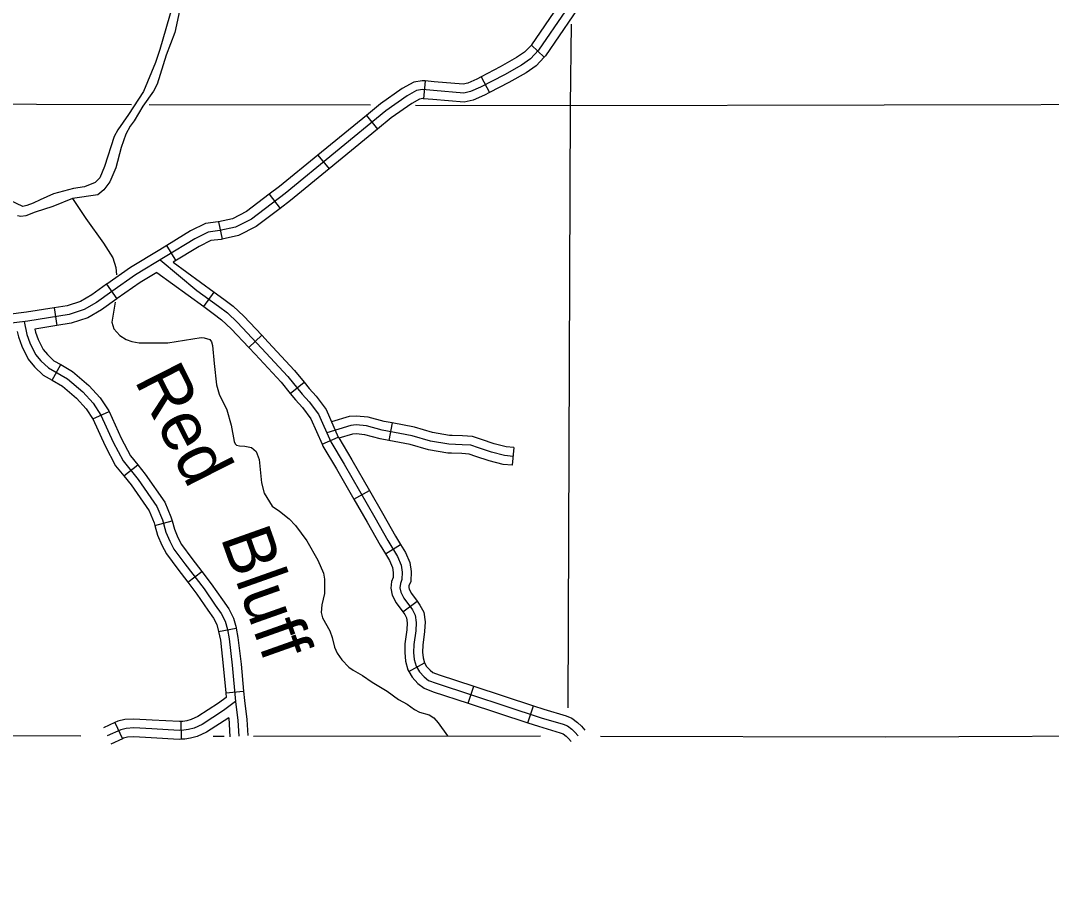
# Model space of a CAD drawing. Extents: x -19 to 366, y -4 to 359.
# Drawn here: x 129.595 to 131.239, y 197.843 to 199.218 of the extents above; entities that cross this region are included whole.
import ezdxf

# ---------------------------------------------------------------- set-up
doc = ezdxf.new("R2010")
doc.units = 0
for name, color, linetype in [('R_Alt Surface', 7, 'Continuous'), ('R_Axis Annot', 7, 'Continuous'), ('R_ROW Annot', 7, 'Continuous'), ('R_Temp Easement', 7, 'Continuous'), ('Sheet Fence', 7, 'Continuous'), ('T_Indications', 7, 'Continuous')]:
    doc.layers.add(name, color=color, linetype=linetype)

msp = doc.modelspace()

# ---------------------------------------------------------------- linework, layer by layer
at = {"layer": 'R_Alt Surface'}
for points in [[(129.0073, 198.0861), (129.0482, 198.0855), (129.434, 198.0792), (129.4695, 198.0791), (129.6913, 198.0783)], [(129.9021, 198.0778), (129.92, 198.0778)], [(129.9664, 198.0778), (130.424, 198.0784)], [(130.5198, 198.0781), (130.9745, 198.0766), (131.4426, 198.0787), (131.466, 198.0787), (131.7638, 198.0787), (132.3344, 198.0804)]]:
    msp.add_lwpolyline(points, dxfattribs=at)
at = {"layer": 'R_Axis Annot'}
for points in [[(130.472, 199.0833), (130.4736, 199.213)], [(129.4687, 199.0856), (129.7722, 199.0849)], [(129.8001, 199.0848), (130.1533, 199.084)], [(130.2248, 199.0838), (130.472, 199.0833)], [(130.472, 199.0833), (131.4723, 199.0854)], [(130.4681, 198.1228), (130.472, 199.0833)]]:
    msp.add_lwpolyline(points, dxfattribs=at)
at = {"layer": 'R_ROW Annot'}
for p, q in [((130.4096, 199.1795), (130.4302, 199.16)), ((130.2404, 199.1222), (130.2379, 199.0939)), ((130.3297, 199.1288), (130.3428, 199.1036)), ((130.1465, 199.0674), (130.1645, 199.0455)), ((130.0691, 199.004), (130.0871, 198.9821)), ((129.9917, 198.9416), (130.0089, 198.919)), ((129.9105, 198.8979), (129.9164, 198.8701)), ((129.8277, 198.8598), (129.8425, 198.8356)), ((129.7323, 198.7983), (129.7489, 198.7752)), ((129.8872, 198.7628), (129.9039, 198.7857)), ((129.6485, 198.7606), (129.6531, 198.7325)), ((129.9589, 198.6974), (129.9796, 198.7168)), ((129.6453, 198.6454), (129.6594, 198.6701)), ((130.0252, 198.624), (130.0473, 198.6419)), ((129.7106, 198.5835), (129.7365, 198.5952)), ((130.0758, 198.5433), (130.1018, 198.5547)), ((129.7598, 198.4928), (129.7819, 198.5106)), ((130.1268, 198.4555), (130.1515, 198.4697)), ((129.8093, 198.4135), (129.8367, 198.4211)), ((130.1769, 198.3686), (130.2012, 198.3833)), ((129.8617, 198.3232), (129.8843, 198.3405)), ((130.2047, 198.276), (130.2276, 198.2929)), ((129.911, 198.2447), (129.9389, 198.2501)), ((130.2145, 198.1808), (130.2393, 198.1948)), ((129.9225, 198.1468), (129.9507, 198.1494)), ((130.3089, 198.1304), (130.3178, 198.1574)), ((130.4039, 198.0992), (130.4128, 198.1261)), ((129.7457, 198.0996), (129.7576, 198.0738)), ((129.8505, 198.1014), (129.8515, 198.073))]:
    msp.add_line(p, q, dxfattribs=at)
for points in [[(130.464, 199.2602), (130.4523, 199.2419), (130.4101, 199.1801), (130.4096, 199.1795)], [(130.4641, 199.2341), (130.4212, 199.1712), (130.4082, 199.1574), (130.3937, 199.1475), (130.3669, 199.1321), (130.3286, 199.1122), (130.3125, 199.1053), (130.3018, 199.103), (130.2535, 199.1068), (130.2359, 199.1084), (130.2267, 199.1068), (130.2114, 199.0984), (130.1777, 199.0747), (130.0168, 198.9428), (129.9632, 198.9022), (129.938, 198.8892), (129.9127, 198.8838), (129.8943, 198.8815), (129.8729, 198.8708), (129.7784, 198.813), (129.7408, 198.7869), (129.7163, 198.7693), (129.6964, 198.7578), (129.6727, 198.7501), (129.6068, 198.7394), (129.2966, 198.7015)], [(130.4879, 199.2449), (130.476, 199.2262), (130.4323, 199.1623), (130.4302, 199.16)], [(130.4096, 199.1795), (130.3989, 199.1683), (130.3861, 199.1595), (130.3601, 199.1446), (130.3297, 199.1288)], [(130.4302, 199.16), (130.4175, 199.1466), (130.4012, 199.1354), (130.3737, 199.1197), (130.3428, 199.1036)], [(130.2404, 199.1222), (130.2353, 199.1227), (130.222, 199.1205), (130.2038, 199.1105), (130.1691, 199.086), (130.1465, 199.0674)], [(130.3297, 199.1288), (130.3225, 199.1251), (130.3082, 199.1189), (130.3008, 199.1173), (130.2547, 199.121), (130.2404, 199.1222)], [(130.3428, 199.1036), (130.3347, 199.0994), (130.3168, 199.0917), (130.3027, 199.0887), (130.2523, 199.0927), (130.2379, 199.0939)], [(130.2379, 199.0939), (130.2365, 199.0941), (130.2314, 199.0932), (130.2189, 199.0863), (130.1863, 199.0633), (130.1645, 199.0455)], [(130.1465, 199.0674), (130.0691, 199.004)], [(130.1645, 199.0455), (130.0871, 198.9821)], [(130.0691, 199.004), (130.0081, 198.954), (129.9917, 198.9416)], [(130.0871, 198.9821), (130.0256, 198.9317), (130.0089, 198.919)], [(129.9917, 198.9416), (129.9556, 198.9143), (129.9331, 198.9027), (129.9105, 198.8979)], [(130.0089, 198.919), (129.9708, 198.8902), (129.9428, 198.8757), (129.9164, 198.8701)], [(129.9105, 198.8979), (129.9103, 198.8979), (129.8901, 198.8953), (129.866, 198.8832), (129.817, 198.8533)], [(129.9164, 198.8701), (129.915, 198.8698), (129.8985, 198.8677), (129.8798, 198.8584), (129.8387, 198.8333)], [(129.817, 198.8533), (129.7706, 198.8249), (129.7326, 198.7985), (129.7323, 198.7983)], [(129.8179, 198.8371), (129.876, 198.7885), (129.9108, 198.7631), (129.925, 198.7525), (129.9409, 198.7371), (129.9793, 198.6963), (130.0213, 198.6514), (130.0443, 198.6231), (130.0555, 198.6106), (130.0703, 198.5911), (130.0898, 198.5468), (130.111, 198.5114), (130.1601, 198.4263), (130.1807, 198.3896), (130.1961, 198.3642), (130.202, 198.3506), (130.2038, 198.3394), (130.2032, 198.3276), (130.2007, 198.3211), (130.1998, 198.3143), (130.2013, 198.3075), (130.2063, 198.2977), (130.2199, 198.2794), (130.2243, 198.2708), (130.2261, 198.2593), (130.2252, 198.246), (130.2222, 198.2241), (130.2219, 198.2114), (130.2228, 198.2002), (130.2261, 198.1893), (130.2311, 198.1804), (130.2385, 198.1724), (130.2456, 198.1668), (130.258, 198.1621), (130.4251, 198.1071), (130.4603, 198.0968), (130.4671, 198.0941), (130.4742, 198.0888), (130.4792, 198.0841), (130.484, 198.0782)], [(129.8387, 198.8333), (129.9039, 198.7857)], [(129.8125, 198.8172), (129.7861, 198.8011), (129.749, 198.7753), (129.7489, 198.7752)], [(129.8125, 198.8172), (129.8872, 198.7628)], [(129.7323, 198.7983), (129.7086, 198.7812), (129.6906, 198.7708), (129.6693, 198.764), (129.6485, 198.7606)], [(129.7489, 198.7752), (129.724, 198.7573), (129.7022, 198.7447), (129.676, 198.7363), (129.6531, 198.7325)], [(129.9039, 198.7857), (129.9193, 198.7745), (129.9342, 198.7633), (129.951, 198.7471), (129.9796, 198.7168)], [(129.6485, 198.7606), (129.6048, 198.7535), (129.5501, 198.7468)], [(129.8872, 198.7628), (129.9024, 198.7517), (129.9158, 198.7416), (129.9308, 198.7271), (129.9589, 198.6974)], [(129.6008, 198.7386), (129.6054, 198.7181), (129.6101, 198.7048), (129.6191, 198.6864), (129.6277, 198.6762), (129.6398, 198.6649), (129.67, 198.6476), (129.6943, 198.6269), (129.7107, 198.6085), (129.7234, 198.5897), (129.7429, 198.5467), (129.7586, 198.5169), (129.7826, 198.4871), (129.8126, 198.4441), (129.8215, 198.4227), (129.827, 198.4031), (129.8333, 198.3885), (129.8398, 198.376), (129.857, 198.3527), (129.8878, 198.3125), (129.9056, 198.2869), (129.9152, 198.2733), (129.9212, 198.2611), (129.9249, 198.2477), (129.9277, 198.2328), (129.9325, 198.1913), (129.938, 198.133), (129.9417, 198.103), (129.9432, 198.0778)], [(129.5897, 198.723), (129.5917, 198.7142), (129.597, 198.6993), (129.6071, 198.6786), (129.6174, 198.6664), (129.6313, 198.6534), (129.6453, 198.6454)], [(129.6531, 198.7325), (129.618, 198.7268)], [(129.618, 198.7268), (129.619, 198.7221), (129.6232, 198.7103), (129.6311, 198.6942), (129.638, 198.686), (129.6483, 198.6764), (129.6594, 198.6701)], [(129.9796, 198.7168), (129.9897, 198.7061), (130.032, 198.6608), (130.0473, 198.6419)], [(129.9589, 198.6974), (129.969, 198.6866), (130.0105, 198.6421), (130.0252, 198.624)], [(129.6594, 198.6701), (129.6782, 198.6593), (129.7042, 198.637), (129.7219, 198.6172), (129.7358, 198.5967), (129.7365, 198.5952)], [(129.6453, 198.6454), (129.6618, 198.636), (129.6843, 198.6167), (129.6995, 198.5997), (129.7109, 198.5828), (129.7106, 198.5835)], [(130.0473, 198.6419), (130.0551, 198.6323), (130.0665, 198.6197), (130.0826, 198.5984), (130.1018, 198.5547)], [(130.0252, 198.624), (130.0335, 198.6138), (130.0446, 198.6016), (130.058, 198.5839), (130.0758, 198.5433)], [(129.7365, 198.5952), (129.7557, 198.5529), (129.7705, 198.5247), (129.7819, 198.5106)], [(129.7106, 198.5835), (129.7302, 198.5404), (129.7467, 198.509), (129.7598, 198.4928)], [(130.0758, 198.5433), (130.0771, 198.5403), (130.0988, 198.5042), (130.1268, 198.4555)], [(130.1018, 198.5547), (130.1024, 198.5534), (130.1233, 198.5186), (130.1515, 198.4697)], [(129.7819, 198.5106), (129.794, 198.4956), (129.8252, 198.451), (129.835, 198.4274), (129.8367, 198.4211)], [(129.7598, 198.4928), (129.7713, 198.4786), (129.8001, 198.4373), (129.8081, 198.4181), (129.8093, 198.4135)], [(130.1515, 198.4697), (130.1724, 198.4333), (130.193, 198.3968), (130.2012, 198.3833)], [(130.1268, 198.4555), (130.1477, 198.4192), (130.1685, 198.3825), (130.1769, 198.3686)], [(129.8093, 198.4135), (129.8136, 198.3984), (129.8204, 198.3824), (129.8277, 198.3684), (129.8457, 198.3442), (129.8617, 198.3232)], [(129.8367, 198.4211), (129.8404, 198.4079), (129.8461, 198.3946), (129.8519, 198.3835), (129.8684, 198.3613), (129.8843, 198.3405)], [(130.2012, 198.3833), (130.2088, 198.3707), (130.2158, 198.3546), (130.218, 198.3401), (130.2173, 198.3246), (130.2145, 198.3175), (130.2142, 198.3149), (130.2148, 198.3123), (130.2184, 198.3053), (130.2276, 198.2929)], [(130.1769, 198.3686), (130.1835, 198.3577), (130.1883, 198.3466), (130.1895, 198.3386), (130.1891, 198.3306), (130.1868, 198.3246), (130.1854, 198.3137), (130.1878, 198.3026), (130.1942, 198.2902), (130.2047, 198.276)], [(129.8843, 198.3405), (129.8993, 198.3209), (129.9172, 198.2951), (129.9275, 198.2806), (129.9346, 198.2661), (129.9387, 198.251), (129.9389, 198.2501)], [(129.8617, 198.3232), (129.8763, 198.3041), (129.8939, 198.2787), (129.903, 198.266), (129.9079, 198.256), (129.911, 198.2445), (129.911, 198.2447)], [(130.2276, 198.2929), (130.232, 198.2869), (130.238, 198.2753), (130.2404, 198.2599), (130.2393, 198.2446), (130.2364, 198.223), (130.2362, 198.2118), (130.2369, 198.2028), (130.2392, 198.1949), (130.2393, 198.1948)], [(130.2047, 198.276), (130.2078, 198.2719), (130.2106, 198.2664), (130.2118, 198.2587), (130.2111, 198.2474), (130.2081, 198.2253), (130.2077, 198.211), (130.2088, 198.1976), (130.2129, 198.1837), (130.2145, 198.1808)], [(129.9389, 198.2501), (129.9418, 198.235), (129.9467, 198.1927), (129.9507, 198.1494)], [(129.911, 198.2447), (129.9137, 198.2307), (129.9184, 198.1898), (129.9225, 198.1468)], [(130.2145, 198.1808), (130.2196, 198.172), (130.2288, 198.162), (130.2385, 198.1543), (130.2532, 198.1487), (130.3089, 198.1304)], [(130.2393, 198.1948), (130.2426, 198.1888), (130.2482, 198.1829), (130.2527, 198.1793), (130.2627, 198.1755), (130.3178, 198.1574)], [(129.9507, 198.1494), (129.9521, 198.1345), (129.9558, 198.1043), (129.9574, 198.0787)], [(130.3178, 198.1574), (130.4128, 198.1261)], [(129.938, 198.133), (129.9187, 198.1187), (129.8848, 198.0965), (129.872, 198.0907), (129.8631, 198.0886), (129.8555, 198.0873), (129.8482, 198.0871), (129.8044, 198.0894), (129.7759, 198.091), (129.7637, 198.0902), (129.7548, 198.0881), (129.7331, 198.0782)], [(129.9231, 198.1396), (129.9106, 198.1303), (129.8779, 198.109), (129.8674, 198.1042), (129.8603, 198.1025), (129.8541, 198.1015), (129.8505, 198.1014)], [(129.9225, 198.1468), (129.9231, 198.1396)], [(130.3089, 198.1304), (130.4039, 198.0992)], [(130.4128, 198.1261), (130.4294, 198.1207), (130.4649, 198.1102), (130.474, 198.1066), (130.4833, 198.0997), (130.4896, 198.0938), (130.495, 198.0872)], [(129.7457, 198.0996), (129.7272, 198.0911)], [(129.8505, 198.1014), (129.8484, 198.1013), (129.8052, 198.1036), (129.7759, 198.1052), (129.7616, 198.1043), (129.7502, 198.1016), (129.7457, 198.0996)], [(129.9272, 198.1072), (129.8916, 198.084), (129.8766, 198.0772), (129.8659, 198.0747), (129.857, 198.0732), (129.8515, 198.073)], [(129.9272, 198.1072), (129.9291, 198.0769)], [(130.4039, 198.0992), (130.4209, 198.0936), (130.4557, 198.0833), (130.4601, 198.0816), (130.465, 198.0779), (130.4688, 198.0744), (130.473, 198.0692)], [(129.7576, 198.0738), (129.739, 198.0653)], [(129.8515, 198.073), (129.8481, 198.0728), (129.8036, 198.0752), (129.776, 198.0767), (129.7658, 198.0761), (129.7594, 198.0746), (129.7576, 198.0738)]]:
    msp.add_lwpolyline(points, dxfattribs=at)
at = {"layer": 'R_Temp Easement'}
for points in [[(129.8376, 199.2422), (129.8172, 199.1725), (129.8103, 199.1519), (129.7911, 199.1057), (129.7674, 199.0689), (129.7501, 199.0443), (129.7446, 199.0336), (129.7291, 198.986), (129.7218, 198.968), (129.714, 198.9603), (129.6971, 198.9536), (129.6794, 198.9506), (129.6478, 198.9421), (129.6264, 198.9327), (129.6151, 198.9272), (129.6053, 198.9236), (129.5989, 198.9224), (129.5784, 198.9315)], [(129.8501, 199.2417), (129.841, 199.1994), (129.8275, 199.1635), (129.8128, 199.117), (129.8069, 199.1059), (129.7903, 199.0822), (129.7763, 199.0588), (129.77, 199.0503), (129.763, 199.0373), (129.7554, 199.0163), (129.7469, 198.984), (129.7374, 198.9614), (129.7278, 198.9488), (129.7185, 198.941), (129.6781, 198.9347), (129.6466, 198.922), (129.6184, 198.9132), (129.6033, 198.9073), (129.5954, 198.9064), (129.5905, 198.9071)], [(129.6781, 198.9347), (129.6992, 198.9032), (129.7276, 198.8639), (129.7421, 198.8403), (129.7469, 198.8249), (129.7479, 198.8133)], [(129.7462, 198.7694), (129.7407, 198.7379), (129.744, 198.7273), (129.7532, 198.7165), (129.7636, 198.7103), (129.7727, 198.707), (129.7845, 198.7046), (129.8299, 198.7047), (129.883, 198.7134), (129.8879, 198.7127), (129.8967, 198.7099), (129.8994, 198.7065), (129.9014, 198.7005), (129.9039, 198.6721), (129.9076, 198.638), (129.9117, 198.6229), (129.9239, 198.5981), (129.9308, 198.5736), (129.9358, 198.5475), (129.9374, 198.5441), (129.9397, 198.5419), (129.9443, 198.5405), (129.9526, 198.5402), (129.9636, 198.5382), (129.971, 198.5315), (129.9754, 198.5187), (129.9795, 198.4816), (129.9836, 198.465), (129.9961, 198.4444), (130.008, 198.4366), (130.0234, 198.4244), (130.0334, 198.4136), (130.0517, 198.3893), (130.0693, 198.3582), (130.0784, 198.3379), (130.0797, 198.328), (130.0798, 198.3053), (130.0756, 198.2874), (130.0747, 198.2748), (130.0768, 198.2665), (130.0882, 198.2459), (130.0922, 198.2349), (130.0959, 198.2195), (130.1002, 198.2101), (130.1076, 198.1996), (130.1188, 198.1877), (130.1253, 198.1829), (130.1403, 198.1744), (130.1556, 198.1637), (130.1797, 198.1494), (130.1977, 198.1361), (130.2115, 198.1288), (130.2234, 198.1203), (130.231, 198.1163), (130.2466, 198.1121), (130.2543, 198.1069), (130.2612, 198.0994)], [(130.2612, 198.0994), (130.2758, 198.0782)]]:
    msp.add_lwpolyline(points, dxfattribs=at)
at = {"layer": 'Sheet Fence'}
for points in [[(132.1027, 1.3746), (131.9232, 9.99), (131.7429, 18.6056), (131.5621, 27.2214), (131.3806, 35.8373), (131.1985, 44.4533), (131.0158, 53.0695), (130.8324, 61.6859), (130.6485, 70.3024), (130.4639, 78.919), (130.2786, 87.5358), (130.0928, 96.1527), (129.9063, 104.7698), (129.7193, 113.387), (129.5316, 122.0044), (129.3433, 130.6219), (129.1543, 139.2396), (128.9648, 147.8575), (128.7746, 156.4754), (128.5838, 165.0936), (128.3925, 173.7119), (128.2005, 182.3303), (128.0078, 190.9489), (127.8146, 199.5676), (127.6208, 208.1865), (127.4264, 216.8056), (127.2313, 225.4247), (127.0357, 234.0441), (126.8394, 242.6636), (126.6425, 251.2833), (126.4451, 259.9031), (126.247, 268.523), (126.0483, 277.1431), (125.849, 285.7634), (125.6492, 294.3838), (125.4487, 303.0044), (125.2476, 311.6252), (125.0459, 320.2461), (124.8437, 328.8671), (124.6408, 337.4883), (124.4373, 346.1097)], [(0, 198.1326), (7.1014, 198.137), (14.2028, 198.1503), (21.3042, 198.1724), (28.4055, 198.2034), (35.5068, 198.2433), (42.6081, 198.292), (49.7092, 198.3496), (56.8103, 198.4161), (63.9113, 198.4913), (71.0123, 198.5755), (78.1131, 198.6685), (85.2137, 198.7704), (92.3143, 198.8811), (99.4147, 199.0007), (106.5149, 199.1291), (113.615, 199.2664), (120.7149, 199.4126), (127.8146, 199.5676), (134.9141, 199.7315), (142.0135, 199.9042), (149.1125, 200.0858), (156.2114, 200.2762), (163.31, 200.4755), (170.4084, 200.6837), (177.5065, 200.9007), (184.6043, 201.1265), (191.7018, 201.3612), (198.799, 201.6048), (205.896, 201.8572), (212.9926, 202.1185), (220.0888, 202.3886), (227.1848, 202.6676), (234.2803, 202.9554), (241.3755, 203.2521), (248.4704, 203.5576), (255.5648, 203.872), (262.6589, 204.1952), (269.7525, 204.5273), (276.8457, 204.8682), (283.9385, 205.218), (291.0309, 205.5766), (298.1228, 205.9441), (305.2142, 206.3204), (312.3051, 206.7056), (319.3956, 207.0996), (326.4856, 207.5024), (333.5751, 207.9141), (340.664, 208.3347)], [(0, 189.5162), (7.1121, 189.5206), (14.2243, 189.5339), (21.3364, 189.556), (28.4484, 189.5869), (35.5605, 189.6267), (42.6725, 189.6754), (49.7844, 189.7329), (56.8962, 189.7992), (64.0079, 189.8744), (71.1196, 189.9584), (78.2311, 190.0512), (85.3425, 190.1529), (92.4538, 190.2635), (99.5649, 190.3829), (106.6759, 190.5111), (113.7867, 190.6482), (120.8974, 190.7941), (128.0078, 190.9489), (135.1181, 191.1125), (142.2282, 191.2849), (149.338, 191.4662), (156.4476, 191.6563), (163.5569, 191.8553), (170.666, 192.0631), (177.7749, 192.2798), (184.8835, 192.5053), (191.9917, 192.7396), (199.0997, 192.9828), (206.2074, 193.2348), (213.3147, 193.4956), (220.4218, 193.7653), (227.5285, 194.0438), (234.6348, 194.3312), (241.7408, 194.6274), (248.8464, 194.9324), (255.9516, 195.2463), (263.0564, 195.569), (270.1608, 195.9005), (277.2648, 196.2409), (284.3683, 196.5901), (291.4715, 196.9481), (298.5741, 197.315), (305.6763, 197.6907), (312.7781, 198.0753), (319.8793, 198.4686), (326.9801, 198.8708), (334.0804, 199.2818), (341.1801, 199.7017)]]:
    msp.add_spline(points, degree=3, dxfattribs=at)
at = {"layer": 'T_Indications'}
for p, q in [((130.1879, 198.5772), (130.1825, 198.5493)), ((130.3816, 198.5381), (130.3791, 198.5098))]:
    msp.add_line(p, q, dxfattribs=at)
for points in [[(130.1879, 198.5772), (130.1749, 198.5797), (130.1492, 198.5864), (130.1303, 198.5882), (130.1191, 198.5872), (130.0912, 198.5788)], [(130.2835, 198.5572), (130.2793, 198.5573), (130.2522, 198.562), (130.2231, 198.5704), (130.1879, 198.5772)], [(130.3804, 198.5239), (130.3669, 198.5251), (130.3462, 198.5305), (130.3254, 198.5374), (130.3131, 198.5416), (130.2993, 198.5424), (130.2778, 198.5432), (130.249, 198.5482), (130.2198, 198.5566), (130.1717, 198.5658), (130.1468, 198.5724), (130.1303, 198.5739), (130.1218, 198.5731), (130.0833, 198.5616)], [(130.1825, 198.5493), (130.1686, 198.552), (130.1443, 198.5583), (130.1302, 198.5597), (130.1245, 198.5591), (130.1029, 198.5527)], [(130.2824, 198.5288), (130.2763, 198.529), (130.2458, 198.5343), (130.2164, 198.5428), (130.1825, 198.5493)], [(130.3816, 198.5381), (130.3693, 198.5391), (130.3502, 198.5441), (130.33, 198.5509), (130.3159, 198.5557), (130.2999, 198.5566), (130.2835, 198.5572)], [(130.3791, 198.5098), (130.3645, 198.511), (130.3421, 198.5169), (130.3209, 198.5239), (130.3104, 198.5276), (130.2986, 198.5282), (130.2824, 198.5288)]]:
    msp.add_lwpolyline(points, dxfattribs=at)

# ---------------------------------------------------------------- texts
at = {"layer": 'R_Temp Easement'}
for s, rotation, p in [('Red', 296.8463, (129.7759, 198.6453)), ('Bluff', 289.5221, (129.9136, 198.3946))]:
    msp.add_text(s, height=0.08, rotation=rotation, dxfattribs=at).set_placement(p)

doc.saveas('drawing.dxf')
